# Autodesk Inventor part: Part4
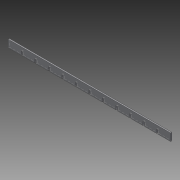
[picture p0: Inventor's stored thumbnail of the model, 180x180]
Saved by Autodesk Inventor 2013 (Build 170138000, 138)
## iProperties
Created: 2013-06
Part Number: Part4
Material: Generic
Document SubType Name: Modeling
Designer: jpfenske
Density: 1 g/cm^3
Author: jpfenske
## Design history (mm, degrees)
sketch "Sketch1"
  geometry: L1 (0, 0)-(838.2, 0); L2 (838.2, 0)-(838.2, 38.1); L3 (838.2, 38.1)-(0, 38.1); L4 (0, 38.1)-(0, 0); L5 (66.675, 0)-(66.675, 19.05); L6 (66.675, 19.05)-(73.025, 19.05); L7 (73.025, 19.05)-(73.025, 0); L8 (73.025, 0)-(66.675, 0); L9 (142.875, 0)-(136.525, 0); L10 (136.525, 0)-(136.525, 19.05); L11 (142.875, 19.05)-(142.875, 0); L12 (136.525, 19.05)-(142.875, 19.05); L13 (212.725, 0)-(206.375, 0); L14 (206.375, 0)-(206.375, 19.05); L15 (212.725, 19.05)-(212.725, 0); L16 (206.375, 19.05)-(212.725, 19.05); L17 (282.575, 0)-(276.225, 0); L18 (276.225, 0)-(276.225, 19.05); L19 (282.575, 19.05)-(282.575, 0); L20 (276.225, 19.05)-(282.575, 19.05); L21 (352.425, 0)-(346.075, 0); L22 (346.075, 0)-(346.075, 19.05); L23 (352.425, 19.05)-(352.425, 0); L24 (346.075, 19.05)-(352.425, 19.05); L25 (422.275, 0)-(415.925, 0); L26 (415.925, 0)-(415.925, 19.05); L27 (422.275, 19.05)-(422.275, 0); L28 (415.925, 19.05)-(422.275, 19.05); L29 (492.125, 0)-(485.775, 0); L30 (485.775, 0)-(485.775, 19.05); L31 (492.125, 19.05)-(492.125, 0); L32 (485.775, 19.05)-(492.125, 19.05); L33 (561.975, 0)-(555.625, 0); L34 (555.625, 0)-(555.625, 19.05); L35 (561.975, 19.05)-(561.975, 0); L36 (555.625, 19.05)-(561.975, 19.05); L37 (631.825, 0)-(625.475, 0); L38 (625.475, 0)-(625.475, 19.05); L39 (631.825, 19.05)-(631.825, 0); L40 (625.475, 19.05)-(631.825, 19.05); L41 (701.675, 0)-(695.325, 0); L42 (695.325, 0)-(695.325, 19.05); L43 (701.675, 19.05)-(701.675, 0); L44 (695.325, 19.05)-(701.675, 19.05); L45 (771.525, 0)-(765.175, 0); L46 (765.175, 0)-(765.175, 19.05); L47 (771.525, 19.05)-(771.525, 0); L48 (765.175, 19.05)-(771.525, 19.05)
  constraints: 96 end point, 4 parallel, 3 perpendicular, 2 horizontal, 1 point on line, 80 other
  dimensions: "d0" = 838.2 distance of L3.end L2.end; "d1" = 38.1 distance of L1.end L2.end; "d2" = 19.05 distance of L5.start L5.end; "d3" = 6.35 distance of L5.end L6.end; "d6" = 69.85 distance of L7.end L9.start
extrude "Extrusion1" new body sketch "Sketch1" distance "d11" = 6.35; taper "d12" = 0 deg
body "Solid1"
other parameters: "d9" = 25.4
